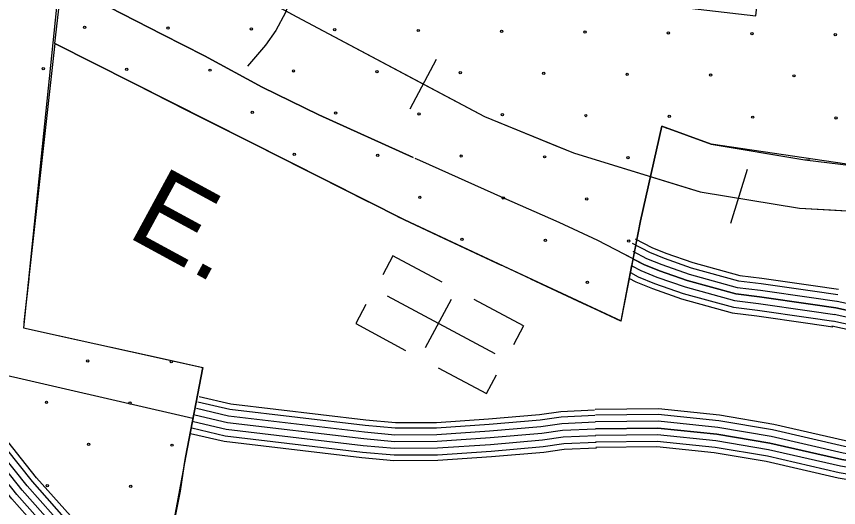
# Model space of a CAD drawing. Extents: x 1788175 to 1969470, y 584502 to 738744.
# Drawn here: x 1817172 to 1820962, y 676025 to 678289 of the extents above; entities that cross this region are included whole.
import ezdxf

# ---------------------------------------------------------------- set-up
doc = ezdxf.new("R2010")
doc.units = 0
for name, color, linetype in [('DESIGN - CONTOURS - Intermediate with optional Text', 7, 'Continuous'), ('DESIGN - EROSION CONTROL - Devices', 7, 'Continuous'), ('DESIGN - ROW - Right-of-Way and Easement Labels', 7, 'Continuous'), ('DESIGN - SCRATCH - User 1', 7, 'Continuous'), ('DESIGN - UTILITIES - Cable (Underground) with Text', 7, 'Continuous'), ('SURVEY - CONTOURS - Index with Text', 7, 'Continuous'), ('SURVEY - CONTOURS - Intermediate with optional Text', 7, 'Continuous'), ('SURVEY - CONTROL with Text', 7, 'Continuous'), ('SURVEY - DRAINAGE - Area Shapes', 7, 'Continuous'), ('SURVEY - TRANSPORTATION - Roads', 7, 'Continuous'), ('SURVEY - VEGETATION - Features with Text', 7, 'Continuous')]:
    doc.layers.add(name, color=color, linetype=linetype)

msp = doc.modelspace()

# ---------------------------------------------------------------- linework, layer by layer
at = {"layer": 'DESIGN - CONTOURS - Intermediate with optional Text'}
for p, q in [((1818987.1, 677862.5), (1819109, 678092.1)), ((1820465.6, 677336.4), (1820542.3, 677584.8))]:
    msp.add_line(p, q, dxfattribs=at)
for points in [[(1815552.9, 680339.1), (1815884.1, 680079.8), (1816436, 679578.8), (1816707.8, 679332.6), (1817064.4, 679077.8), (1817389.2, 678879.4), (1817550.3, 678784.5), (1818465, 678286.6)], [(1818219.1, 678420.5), (1818465, 678286.6)], [(1818465, 678286.6), (1819329.5, 677828), (1819739.9, 677660.6), (1820323.7, 677480.6), (1820782.6, 677404.6), (1821189.6, 677382.1), (1821920.8, 677333.9), (1822664.2, 677286), (1823247.2, 677248.1), (1823684.2, 677213.4)], [(1818465, 678286.6), (1819048.1, 677977.3)], [(1819048.1, 677977.3), (1819329.5, 677828), (1819645.6, 677699.1)], [(1819645.6, 677699.1), (1819739.9, 677660.6), (1820273.3, 677496.1)], [(1820273.3, 677496.1), (1820323.7, 677480.6), (1820782.6, 677404.6), (1820924.5, 677396.7)], [(1820924.5, 677396.7), (1821189.6, 677382.1), (1821583.2, 677356.2)]]:
    msp.add_lwpolyline(points, dxfattribs=at)
at = {"layer": 'DESIGN - EROSION CONTROL - Devices'}
for centre in [(1817486.1, 678239.1), (1817870.6, 678235.4), (1818255.2, 678231.7), (1818639.7, 678227.9), (1819024.3, 678224.2), (1819408.8, 678220.5), (1819793.4, 678216.7), (1820178, 678213), (1820562.5, 678209.3), (1820947.1, 678205.5), (1817295.7, 678048.7), (1817680.2, 678045), (1818064.8, 678041.2), (1818449.3, 678037.5), (1818833.9, 678033.8), (1819218.4, 678030), (1819603, 678026.3), (1819987.5, 678022.6), (1820372.1, 678018.8), (1820756.7, 678015.1), (1818258.9, 677847.1), (1818643.5, 677843.4), (1819028, 677839.6), (1819412.6, 677835.9), (1819797.1, 677832.2), (1820181.7, 677828.4), (1820566.2, 677824.7), (1820950.8, 677821), (1818453.1, 677653), (1818837.6, 677649.2), (1819222.2, 677645.5), (1819606.7, 677641.8), (1819991.3, 677638), (1819031.8, 677455.1), (1819416.3, 677451.4), (1819800.9, 677447.6), (1819225.9, 677260.9), (1819610.5, 677257.2), (1819995, 677253.5), (1819804.6, 677063.1), (1817501, 676700.9), (1817885.6, 676697.2), (1817310.6, 676510.5), (1817695.2, 676506.8), (1817504.8, 676316.4), (1817889.3, 676312.6), (1817314.3, 676126), (1817698.9, 676122.2)]:
    msp.add_circle(centre, 5.28, dxfattribs=at)
at = {"layer": 'DESIGN - SCRATCH - User 1'}
for p, q in [((1817381.5, 678574.3), (1817204.1, 676852.7)), ((1819958.7, 676883.9), (1818960.8, 677350.9)), ((1820048.4, 677346.6), (1819958.7, 676883.9)), ((1817204.1, 676852.7), (1818030.7, 676670.6))]:
    msp.add_line(p, q, dxfattribs=at)
for points in [[(1818960.8, 677350.9), (1817348.3, 678164.2), (1817453.6, 679067.7), (1818143.9, 678728.7), (1818442.6, 678566.6), (1818596.8, 678535.2), (1818684.3, 678553.1), (1818753.1, 678630.4), (1818776, 678690.6), (1818824.1, 678977.9), (1819190.7, 678914.3), (1819237.2, 679120.8), (1819456.5, 679101.8), (1819487.9, 679308.2), (1820018.4, 679266.2), (1819943.3, 678367), (1820581.3, 678291.3), (1820634.4, 678779.4), (1820280.5, 678860.6), (1820548.7, 680912)], [(1820375.5, 677700.1), (1820147.6, 677782.6), (1820048.4, 677346.6)], [(1822802.8, 677057.7), (1822775.3, 676859), (1821690.6, 677038.3), (1821639.7, 677566.7), (1821135.9, 677587.8), (1820375.5, 677700.1)], [(1818030.7, 676670.6), (1817951.9, 676255.3), (1817848.5, 675700.2), (1817808.4, 675501.3), (1817793.2, 675433.7), (1817781.1, 675399.9), (1817803.7, 675359.3), (1817813.4, 675332.5), (1817778.3, 675314.6), (1817535.2, 675286.3), (1817565.6, 675046.9), (1817806.8, 675077.3), (1817779.3, 675311.3), (1817816.3, 675325.5), (1817830.7, 675158.1), (1817898.6, 675106.1), (1817953.9, 675100.3)]]:
    msp.add_lwpolyline(points, dxfattribs=at)
at = {"layer": 'DESIGN - UTILITIES - Cable (Underground) with Text'}
for p, q in [((1818907.9, 677185), (1818860.9, 677097.1)), ((1819134.2, 677063.7), (1818907.9, 677184.9)), ((1819176.2, 676984.4), (1819056.4, 676760.9)), ((1819510.2, 676862.3), (1819282.7, 676984.2)), ((1818783.3, 676960.7), (1818736.4, 676873.3)), ((1818736.2, 676872.8), (1818966.1, 676749.6)), ((1819510, 676862.1), (1819463.1, 676774.4)), ((1819116.7, 676668.8), (1819338.4, 676550.1)), ((1819338.5, 676550.2), (1819384.8, 676636.8))]:
    msp.add_line(p, q, dxfattribs=at)
msp.add_lwpolyline([(1818881, 677000.5), (1819377.3, 676734.5)], dxfattribs=at)
at = {"layer": 'SURVEY - CONTOURS - Index with Text'}
for points in [[(1817370.9, 678486.6), (1817469.4, 678416.1), (1817599.2, 678332.1), (1817844.9, 678205.9), (1818038.6, 678107.8), (1818304.2, 677963.6), (1818565.9, 677835.4), (1819001.4, 677638.5)], [(1819001.4, 677638.5), (1818565.9, 677835.4), (1818304.2, 677963.6), (1818038.6, 678107.8), (1817844.9, 678205.9), (1817599.2, 678332.1), (1817469.4, 678416.1), (1817437.3, 678439.1)], [(1828171.9, 678007.3), (1826420.5, 677430.1), (1824826.1, 676899.1), (1824110.7, 676694.4), (1823699.5, 676627.8), (1823352.3, 676602.3), (1823147.3, 676606.7), (1822910.6, 676631.6), (1822718.7, 676643.9), (1822564.7, 676657.7), (1822396.5, 676687.5), (1822193.6, 676722), (1821946.8, 676772.9), (1821404.9, 676877.6), (1820955.8, 676975.6)], [(1828181.6, 677977.9), (1826430.2, 677400.6), (1824835.3, 676869.5), (1824117.5, 676664.1), (1823703.1, 676597), (1823353.1, 676571.2), (1823145.4, 676575.8), (1822908, 676600.7), (1822716.3, 676613), (1822560.6, 676626.9), (1822391.2, 676657), (1822187.8, 676691.5), (1821940.7, 676742.5), (1821398.6, 676847.2), (1820949.2, 676945.3)], [(1820949.2, 676945.3), (1821398.6, 676847.2), (1821940.7, 676742.5), (1822187.8, 676691.5), (1822391.2, 676657), (1822560.6, 676626.9), (1822716.3, 676613), (1822908, 676600.7), (1823145.4, 676575.8), (1823353.1, 676571.2), (1823703.1, 676597), (1824117.5, 676664.1), (1824835.3, 676869.5), (1826430.2, 677400.6), (1828181.6, 677977.9)], [(1828201, 677919), (1826449.7, 677341.8), (1824853.6, 676810.3), (1824131, 676603.4), (1823710.3, 676535.4), (1823354.7, 676509.2), (1823141.5, 676513.8), (1822902.7, 676538.9), (1822711.6, 676551.2), (1822552.5, 676565.4), (1822380.6, 676595.9), (1822176.4, 676630.6), (1821928.6, 676681.7), (1821386.1, 676786.5), (1820936, 676884.7)], [(1828191.3, 677948.5), (1826440, 677371.2), (1824844.4, 676839.9), (1824124.2, 676633.7), (1823706.7, 676566.2), (1823353.9, 676540.2), (1823143.4, 676544.8), (1822905.3, 676569.8), (1822713.9, 676582.1), (1822556.5, 676596.2), (1822385.9, 676626.5), (1822182.1, 676661), (1821934.7, 676712.1), (1821392.4, 676816.9), (1820942.6, 676915)], [(1828208.7, 677895.5), (1826457.5, 677318.3), (1824860.9, 676786.7), (1824136.4, 676579.3), (1823713.2, 676510.8), (1823355.4, 676484.5), (1823139.9, 676489.2), (1822900.6, 676514.3), (1822709.7, 676526.5), (1822549.2, 676540.9), (1822376.4, 676571.6), (1822171.8, 676606.3), (1821923.8, 676657.5), (1821381.2, 676762.3), (1820930.7, 676860.6)], [(1820015.1, 677171.1), (1819852.2, 677256.4), (1819674.5, 677338.5), (1819418.8, 677450.7), (1819031.3, 677625), (1819010.1, 677634.6)], [(1820010.8, 677243.3), (1820090.3, 677201.7), (1820157.8, 677174.2), (1820282.8, 677130.5), (1820501.5, 677070.4), (1820605.7, 677057.2), (1820841.8, 677023.9), (1820958.3, 677006.6)], [(1820024.4, 677264.1), (1820100.7, 677224.2), (1820166.6, 677197.3), (1820290.2, 677154.1), (1820506.4, 677094.7), (1820609, 677081.7), (1820845.3, 677048.3), (1820961.9, 677031.1)], [(1820949.2, 676945.3), (1820832.9, 676962.5), (1820597.5, 676995.7), (1820489.3, 677009.5), (1820264.4, 677071.3), (1820135.9, 677116.2), (1820064.2, 677145.4), (1819967, 677196.3)], [(1820013.3, 677207.1), (1820077.2, 677173.6), (1820146.8, 677145.2), (1820273.6, 677100.9), (1820495.4, 677040), (1820601.6, 677026.4), (1820837.3, 676993.2), (1820953.8, 676976)], [(1820013.9, 677171.8), (1820064.2, 677145.4), (1820135.9, 677116.2), (1820264.4, 677071.3), (1820489.3, 677009.5), (1820597.5, 676995.7), (1820832.9, 676962.5), (1820949.2, 676945.3)], [(1820009.4, 677139.1), (1820051.1, 677117.3), (1820124.9, 677087.2), (1820255.2, 677041.7), (1820483.2, 676979), (1820593.3, 676965), (1820828.5, 676931.8), (1820944.7, 676914.6)], [(1819994.9, 677082.7), (1820027.2, 677065.8), (1820104.8, 677034.1), (1820238.3, 676987.5), (1820472.1, 676923.3), (1820585.8, 676908.8), (1820820.4, 676875.7), (1820936.4, 676858.5)], [(1820002.2, 677107.9), (1820038, 677089.1), (1820113.9, 677058.2), (1820245.9, 677012.1), (1820477.1, 676948.5), (1820589.2, 676934.3), (1820824, 676901.2), (1820940.1, 676884)]]:
    msp.add_lwpolyline(points, dxfattribs=at)
at = {"layer": 'SURVEY - CONTOURS - Intermediate with optional Text'}
msp.add_lwpolyline([(1817985.6, 676436), (1816670, 676738.9)], dxfattribs=at)
at = {"layer": 'SURVEY - CONTROL with Text'}
for points in [[(1817595.7, 675291.7), (1817595.3, 675293.6), (1817560.8, 675403.8), (1817528.6, 675497.7), (1817448.7, 675666.4), (1817415, 675736.2), (1817328.2, 675865.2), (1817150.6, 676065.5), (1816969, 676292.3), (1816138.7, 677267), (1815469.3, 678068.6), (1815271.6, 678359.7), (1815204.1, 678508.3), (1815165.4, 678636.4), (1815159, 678712), (1815154.9, 678801.6), (1815257.7, 679432), (1815287.1, 679657.4)], [(1817626.6, 675295.1), (1817625.3, 675301.4), (1817590.3, 675413.4), (1817557.3, 675509.4), (1817476.7, 675679.7), (1817441.9, 675751.7), (1817352.8, 675884.2), (1817174.3, 676085.5), (1816992.9, 676312), (1816162.4, 677287), (1815494.1, 678087.3), (1815298.7, 678374.9), (1815233.2, 678519.2), (1815196, 678642.3), (1815189.9, 678714.1), (1815186, 678799.8), (1815288.3, 679427.5), (1815316.7, 679644.6)], [(1817657.6, 675298.6), (1817655.4, 675309.1), (1817619.7, 675423.1), (1817586.1, 675521.1), (1817504.6, 675693.1), (1817468.9, 675767.1), (1817377.3, 675903.2), (1817198, 676105.5), (1817016.8, 676331.8), (1816186.1, 677307), (1815518.9, 678105.9), (1815325.8, 678390.2), (1815262.3, 678530.2), (1815226.7, 678648.1), (1815220.9, 678716.1), (1815217.1, 678798), (1815319, 679423), (1815347.1, 679637.9)], [(1817688.5, 675302), (1817685.4, 675316.9), (1817649.2, 675432.8), (1817614.8, 675532.8), (1817532.6, 675706.5), (1817495.8, 675782.6), (1817401.9, 675922.2), (1817221.7, 676125.5), (1817040.7, 676351.5), (1816209.8, 677327), (1815543.6, 678124.6), (1815353, 678405.4), (1815291.4, 678541.1), (1815257.3, 678654), (1815251.8, 678718.1), (1815248.2, 678796.2), (1815349.7, 679418.5), (1815378.3, 679637.7)], [(1817719.4, 675305.4), (1817715.5, 675324.7), (1817678.7, 675442.4), (1817643.6, 675544.5), (1817560.6, 675719.9), (1817522.8, 675798.1), (1817426.5, 675941.3), (1817245.4, 676145.5), (1817064.6, 676371.2), (1816233.5, 677347), (1815568.4, 678143.3), (1815380.1, 678420.6), (1815320.4, 678552), (1815287.9, 678659.9), (1815282.8, 678720.1), (1815279.4, 678794.4), (1815380.4, 679414), (1815410.5, 679644.5)], [(1817745.1, 675308.3), (1817740.4, 675331.2), (1817703.1, 675450.5), (1817667.4, 675554.2), (1817583.8, 675731), (1817545.1, 675810.9), (1817446.8, 675957), (1817265.1, 676162.1), (1817084.4, 676387.6), (1816253.2, 677363.5), (1815589, 678158.8), (1815402.6, 678433.2), (1815344.6, 678561.1), (1815313.3, 678664.7), (1815308.4, 678721.8), (1815305.2, 678792.9), (1815405.8, 679410.2), (1815437.9, 679655.9)]]:
    msp.add_lwpolyline(points, dxfattribs=at)
at = {"layer": 'SURVEY - DRAINAGE - Area Shapes'}
msp.add_lwpolyline([(1818478.5, 678559.6), (1818465.4, 678455.8), (1818413.1, 678306.5), (1818368.4, 678224.3), (1818319.9, 678157.1), (1818237.8, 678060)], dxfattribs=at)
at = {"layer": 'SURVEY - TRANSPORTATION - Roads'}
for points in [[(1822861.3, 676674), (1822522.6, 676452.7), (1822173.8, 676310.4), (1821960.1, 676228.6), (1821811, 676203.8), (1821726.6, 676210), (1821623.4, 676224.7), (1821467, 676252.4), (1820994.7, 676331.9), (1820663.2, 676408), (1820412.9, 676450.7), (1820132.4, 676479.3), (1819840.6, 676476.2)], [(1822875.3, 676652.5), (1822534.6, 676429.8), (1822183.2, 676286.5), (1821966.9, 676203.6), (1821812.2, 676177.9), (1821723.9, 676184.4), (1821619.3, 676199.3), (1821462.6, 676227.1), (1820989.7, 676306.6), (1820658.2, 676382.8), (1820409.5, 676425.2), (1820131.2, 676453.6), (1819840.9, 676450.5)], [(1822892.3, 676626.5), (1822549, 676402.2), (1822194.6, 676257.7), (1821975, 676173.6), (1821813.6, 676146.7), (1821720.6, 676153.5), (1821614.4, 676168.6), (1821457.3, 676196.5), (1820983.6, 676276.2), (1820652.1, 676352.4), (1820405.3, 676394.5), (1820129.8, 676422.6), (1819841.2, 676419.5)], [(1819841.5, 676388.5), (1820128.4, 676391.6), (1820401.1, 676363.7), (1820646, 676322), (1820977.6, 676245.8), (1821452.1, 676166), (1821609.5, 676138), (1821717.2, 676122.7), (1821815, 676115.5), (1821983.2, 676143.5), (1822206, 676228.9), (1822563.5, 676374.7), (1822909.2, 676600.5)], [(1822909.2, 676600.5), (1822563.5, 676374.7), (1822206, 676228.9), (1821983.2, 676143.5), (1821815, 676115.5), (1821717.2, 676122.7), (1821609.5, 676138), (1821452.1, 676166), (1820977.6, 676245.8), (1820646, 676322), (1820401.1, 676363.7), (1820128.4, 676391.6), (1819841.5, 676388.5)], [(1822926.2, 676574.6), (1822578, 676347.1), (1822217.4, 676200), (1821991.4, 676113.4), (1821816.5, 676084.3), (1821713.9, 676091.9), (1821604.6, 676107.4), (1821446.8, 676135.4), (1820971.5, 676215.4), (1820639.9, 676291.6), (1820396.9, 676333), (1820127, 676360.5), (1819841.9, 676357.5)], [(1818008.8, 676512.6), (1818155.5, 676478.2), (1818780.2, 676404.2), (1818918.3, 676391.8), (1819109.3, 676392.6), (1819350.7, 676409.1), (1819586.5, 676429.5), (1819683.8, 676443.1), (1819838.6, 676450.4)], [(1818014.4, 676536.7), (1818159.8, 676502.6), (1818782.7, 676428.8), (1818919.3, 676416.5), (1819108.4, 676417.4), (1819348.8, 676433.7), (1819583.8, 676454.1), (1819681.5, 676467.8), (1819837.5, 676475.1)], [(1822943.1, 676548.6), (1822592.4, 676319.5), (1822228.8, 676171.2), (1821999.6, 676083.4), (1821817.9, 676053.1), (1821710.6, 676061), (1821599.8, 676076.8), (1821441.5, 676104.9), (1820965.5, 676185), (1820633.9, 676261.2), (1820392.7, 676302.3), (1820125.5, 676329.5), (1819842.2, 676326.5)], [(1822956.7, 676527.9), (1822603.9, 676297.5), (1822237.9, 676148.2), (1822006.1, 676059.4), (1821819, 676028.3), (1821707.9, 676036.4), (1821595.9, 676052.4), (1821437.3, 676080.5), (1820960.6, 676160.7), (1820629, 676236.9), (1820389.4, 676277.8), (1820124.4, 676304.8), (1819842.5, 676301.7)], [(1818001.7, 676482.4), (1818150.2, 676447.7), (1818777, 676373.4), (1818916.9, 676360.8), (1819110.4, 676361.6), (1819353.1, 676378.2), (1819590, 676398.7), (1819686.7, 676412.2), (1819840.1, 676419.4)], [(1817994.6, 676452.2), (1818144.8, 676417.1), (1818773.8, 676342.6), (1818915.6, 676329.8), (1819111.5, 676330.7), (1819355.5, 676347.3), (1819593.5, 676367.9), (1819689.6, 676381.3), (1819841.5, 676388.5)], [(1817994.6, 676452.2), (1818144.8, 676417.1), (1818773.8, 676342.6), (1818915.6, 676329.8), (1819111.5, 676330.7), (1819355.5, 676347.3), (1819593.5, 676367.9), (1819689.6, 676381.3), (1819841.5, 676388.5)], [(1817987.6, 676422.1), (1818139.4, 676386.5), (1818770.5, 676311.7), (1818914.3, 676298.8), (1819112.6, 676299.7), (1819357.9, 676316.3), (1819597, 676337.1), (1819692.4, 676350.4), (1819843, 676357.5)], [(1817974.6, 676366.8), (1818129.6, 676330.5), (1818764.7, 676255.3), (1818911.9, 676242), (1819114.7, 676243), (1819362.3, 676259.8), (1819603.4, 676280.7), (1819697.7, 676293.9), (1819845.6, 676300.8)], [(1817980.5, 676391.9), (1818134, 676355.9), (1818767.3, 676280.9), (1818913, 676267.8), (1819113.8, 676268.7), (1819360.3, 676285.4), (1819600.5, 676306.3), (1819695.3, 676319.5), (1819844.4, 676326.5)]]:
    msp.add_lwpolyline(points, dxfattribs=at)
at = {"layer": 'SURVEY - VEGETATION - Features with Text'}
for points in [[(1817348.3, 678164.2), (1817206.6, 676877.7)], [(1817348.3, 678164.2), (1817319.4, 677901.8)], [(1817348.3, 678164.2), (1818960.8, 677350.9), (1819959.7, 676885)], [(1817348.3, 678164.2), (1817584, 678045.3)], [(1817717.9, 677977.8), (1817953.6, 677858.9)], [(1817953.6, 677858.9), (1818189.4, 677740)], [(1819959.7, 676885), (1820048.4, 677346.6), (1820147.6, 677782.6), (1820375.5, 677700.1), (1820807.3, 677628.5), (1821135.9, 677587.8), (1821639.7, 677566.7), (1821690.6, 677038.3)], [(1820094.5, 677549.3), (1820147.6, 677782.6), (1820170.9, 677774.2)], [(1817302.9, 677752.7), (1817274, 677490.3)], [(1820311.9, 677723.1), (1820375.5, 677700.1), (1820569.2, 677668)], [(1818323.3, 677672.4), (1818559, 677553.6)], [(1820569.2, 677668), (1820807.3, 677628.5), (1820829.9, 677627.3)], [(1818559, 677553.6), (1818794.7, 677434.7)], [(1820037.9, 677291.5), (1820048.4, 677346.6), (1820094.5, 677549.3)], [(1817274, 677490.3), (1817245.1, 677227.8)], [(1818928.7, 677367.1), (1818960.8, 677350.9), (1819167.4, 677254.5)], [(1819167.4, 677254.5), (1819406.7, 677142.9)], [(1819959.7, 676885), (1820009.6, 677144.2)], [(1817228.7, 677078.8), (1817206.6, 676877.7)], [(1819542.6, 677079.5), (1819781.9, 676967.9)], [(1819781.9, 676967.9), (1819959.7, 676885)], [(1817204.1, 676852.7), (1818030.7, 676670.6)], [(1817204.1, 676852.7), (1817461.9, 676795.9)], [(1817608.4, 676763.6), (1817866.2, 676706.9)], [(1817866.2, 676706.9), (1818030.7, 676670.6)], [(1817943.3, 675104), (1817936.2, 675211.2), (1817912.9, 675316.8), (1817870, 675460.1), (1817827, 675585.5), (1817848.5, 675700.2), (1817927.6, 676100.8), (1817951.9, 676255.3), (1818030.7, 676670.6)], [(1817984.9, 676429), (1818030.7, 676670.6)], [(1817938.3, 676169.2), (1817951.9, 676255.3), (1817984.9, 676429)]]:
    msp.add_lwpolyline(points, dxfattribs=at)

# ---------------------------------------------------------------- texts
at = {"layer": 'DESIGN - ROW - Right-of-Way and Easement Labels'}
msp.add_text('E.', height=370, rotation=331.5058, dxfattribs=at).set_placement((1817673.8, 677278.1))

doc.saveas('drawing.dxf')
